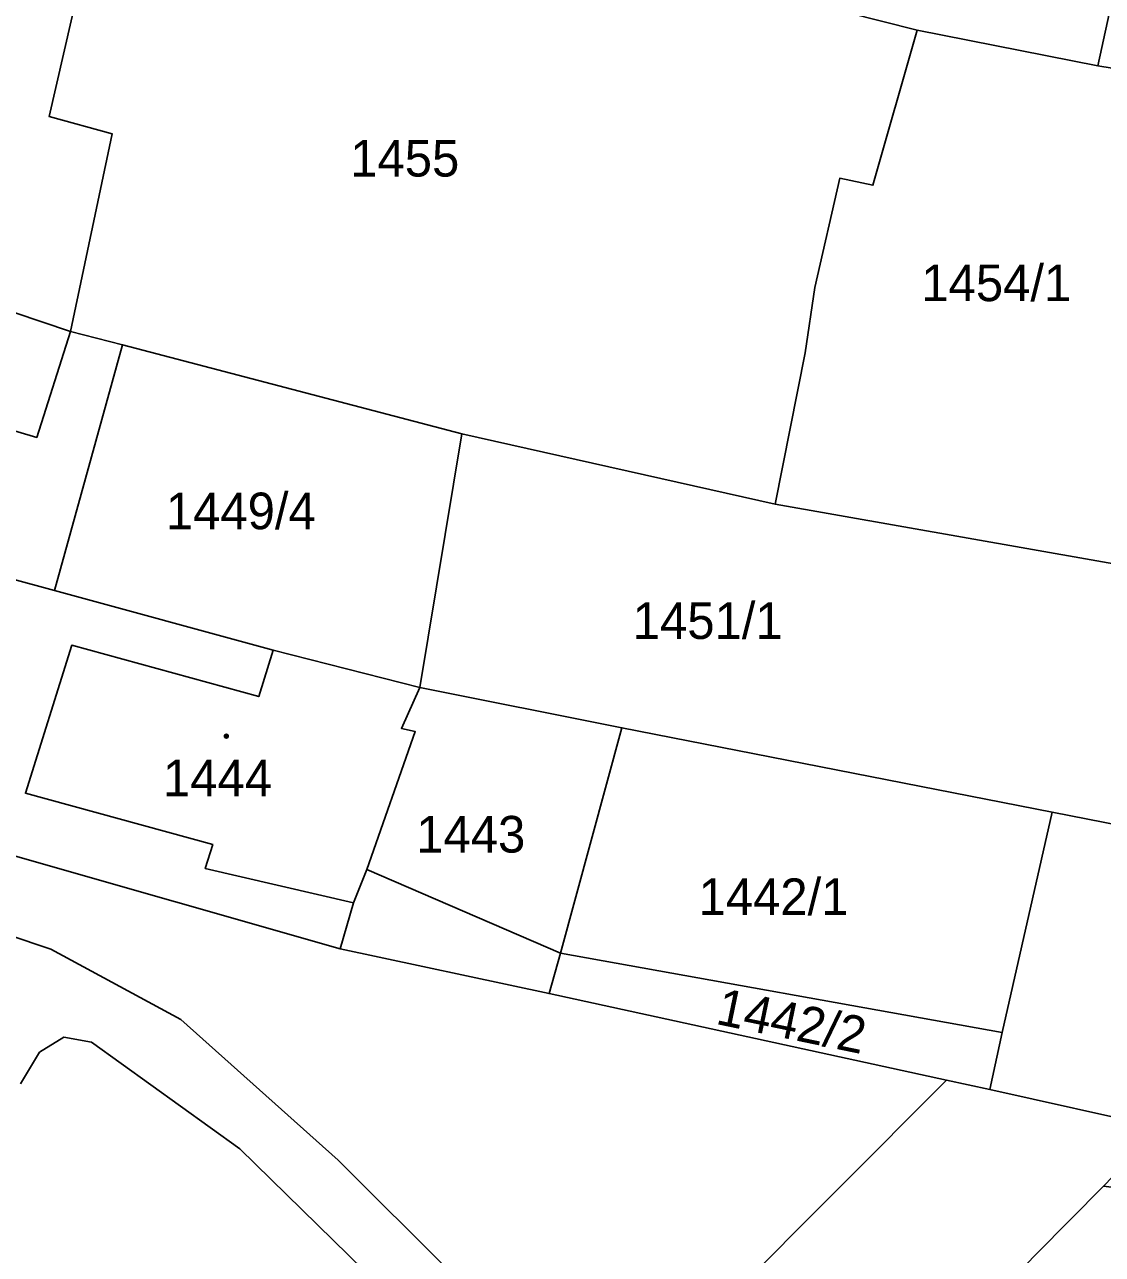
# Model space of a CAD drawing. Extents: x -598934 to -598196, y -1162208 to -1161502.
# Drawn here: x -598595 to -598545.1, y -1161658.4 to -1161601.3 of the extents above; entities that cross this region are included whole.
import ezdxf

# ---------------------------------------------------------------- set-up
doc = ezdxf.new("R2010")
doc.units = 0
for name, color, linetype in [('KN_CAR_KR', 7, 'Continuous'), ('KN_KULTURY', 7, 'Continuous'), ('KN_PARC_CIS_POZ', 7, 'Continuous'), ('KN_PARC_CIS_STAV', 7, 'Continuous'), ('KN_PARC_PLOCHA', 7, 'Continuous'), ('parcely_l', 7, 'Continuous')]:
    doc.layers.add(name, color=color, linetype=linetype)

msp = doc.modelspace()

# ---------------------------------------------------------------- linework, layer by layer
at = {"layer": 'KN_CAR_KR'}
for points in [[(-598609.95, -1161638.83), (-598593.83, -1161644.24)], [(-598570.2, -1161644.42), (-598579.17, -1161640.54)], [(-598593.83, -1161644.24), (-598587.8, -1161647.5)], [(-598587.8, -1161647.5), (-598580.5, -1161654.03)], [(-598593.22, -1161648.32), (-598594.36, -1161649.02)], [(-598591.94, -1161648.56), (-598593.22, -1161648.32)], [(-598595.24, -1161650.49), (-598594.36, -1161649.02)], [(-598591.94, -1161648.56), (-598585.06, -1161653.5)], [(-598585.06, -1161653.5), (-598578.58, -1161659.86)], [(-598580.5, -1161654.03), (-598570, -1161664.51)]]:
    msp.add_lwpolyline(points, dxfattribs=at)
at = {"layer": 'KN_KULTURY'}
for radius in [0.09, 0.0398]:
    msp.add_circle((-598585.69, -1161634.36), radius, dxfattribs=at)
at = {"layer": 'KN_PARC_PLOCHA'}
for points in [[(-598624.11, -1161581.44), (-598590.84, -1161592.28), (-598593.9, -1161605.62), (-598590.99, -1161606.41), (-598592.92, -1161615.58), (-598602.01, -1161612.53), (-598617.23, -1161607.95), (-598636.32, -1161601.91), (-598641.28, -1161599.7), (-598647.1, -1161597.16), (-598637.58, -1161576.44), (-598633.95, -1161578.1), (-598624.47, -1161581.28)], [(-598579.26, -1161595.13), (-598553.66, -1161601.61), (-598555.71, -1161608.8), (-598557.25, -1161608.48), (-598558.4, -1161613.55), (-598558.85, -1161616.58), (-598560.25, -1161623.59), (-598574.77, -1161620.33), (-598590.51, -1161616.21), (-598592.92, -1161615.58), (-598590.99, -1161606.41), (-598593.9, -1161605.62), (-598590.84, -1161592.28)], [(-598592.92, -1161615.58), (-598594.48, -1161620.5), (-598604.3, -1161617.58), (-598628.19, -1161609.89), (-598632.34, -1161608.56), (-598633.12, -1161611.11), (-598637.33, -1161609.86), (-598636.53, -1161607.17), (-598642.58, -1161605.23), (-598641.28, -1161599.7), (-598636.32, -1161601.91), (-598617.23, -1161607.95), (-598602.01, -1161612.53)], [(-598545.28, -1161603.26), (-598535.01, -1161604.94), (-598537.19, -1161614.99), (-598538.62, -1161621.3), (-598528.73, -1161622.73), (-598511.79, -1161625.27), (-598511.94, -1161626.55), (-598512.59, -1161630.77), (-598532.32, -1161628.19), (-598533.65, -1161628.02), (-598539.63, -1161627.23), (-598560.25, -1161623.59), (-598558.85, -1161616.58), (-598558.4, -1161613.55), (-598557.25, -1161608.48), (-598555.71, -1161608.8), (-598553.66, -1161601.61)], [(-598590.51, -1161616.21), (-598593.66, -1161627.61), (-598606.12, -1161624.21), (-598604.3, -1161617.58), (-598594.48, -1161620.5), (-598592.92, -1161615.58)], [(-598574.77, -1161620.33), (-598576.72, -1161632.1), (-598583.52, -1161630.37), (-598593.66, -1161627.61), (-598590.51, -1161616.21)], [(-598560.25, -1161623.59), (-598539.63, -1161627.23), (-598533.65, -1161628.02), (-598534.77, -1161635.43), (-598528.42, -1161636.39), (-598529.24, -1161640.79), (-598531.43, -1161640.62), (-598541.81, -1161638.99), (-598547.4, -1161637.89), (-598567.35, -1161633.97), (-598576.72, -1161632.1), (-598574.77, -1161620.33)], [(-598593.66, -1161627.61), (-598583.52, -1161630.37), (-598584.19, -1161632.52), (-598592.86, -1161630.14), (-598595.01, -1161637.01), (-598586.32, -1161639.39), (-598586.67, -1161640.5), (-598579.79, -1161642.09), (-598580.42, -1161644.22), (-598595.68, -1161639.87), (-598609.56, -1161636.18), (-598606.12, -1161624.21)], [(-598583.52, -1161630.37), (-598576.72, -1161632.1), (-598577.57, -1161634), (-598576.93, -1161634.15), (-598579.17, -1161640.54), (-598579.79, -1161642.09), (-598586.67, -1161640.5), (-598586.32, -1161639.39), (-598595.01, -1161637.01), (-598592.86, -1161630.14), (-598584.19, -1161632.52)], [(-598567.35, -1161633.97), (-598570.2, -1161644.42), (-598570.73, -1161646.3), (-598580.42, -1161644.22), (-598579.79, -1161642.09), (-598579.17, -1161640.54), (-598576.93, -1161634.15), (-598577.57, -1161634), (-598576.72, -1161632.1)], [(-598547.4, -1161637.89), (-598549.72, -1161648.11), (-598570.2, -1161644.42), (-598567.35, -1161633.97)], [(-598529.24, -1161640.79), (-598525.98, -1161640.94), (-598522, -1161641.16), (-598521.79, -1161641.35), (-598513.3, -1161649.15), (-598520.41, -1161657.62), (-598520.79, -1161657.48), (-598523.54, -1161655.94), (-598526.88, -1161655.45), (-598530.26, -1161654.98), (-598533.57, -1161654.46), (-598542.39, -1161652.51), (-598550.29, -1161650.75), (-598549.72, -1161648.11), (-598547.4, -1161637.89), (-598541.81, -1161638.99), (-598531.43, -1161640.62)], [(-598549.72, -1161648.11), (-598550.29, -1161650.75), (-598552.3, -1161650.32), (-598570.73, -1161646.3), (-598570.2, -1161644.42)], [(-598536.1, -1161656.95), (-598543.36, -1161664.75), (-598548.22, -1161669.81), (-598553.01, -1161665.26), (-598553.29, -1161665.01), (-598553.46, -1161664.69), (-598553.52, -1161664.38), (-598553.45, -1161663.96), (-598553.24, -1161663.61), (-598552.96, -1161663.37), (-598548.13, -1161658.38), (-598545.02, -1161655.24), (-598536.87, -1161656.25)]]:
    msp.add_lwpolyline(points, close=True, dxfattribs=at)
for points in [[(-598543.94, -1161597.07), (-598545.28, -1161603.26), (-598553.66, -1161601.61), (-598579.26, -1161595.13)], [(-598535.01, -1161604.94), (-598545.28, -1161603.26), (-598543.94, -1161597.07)], [(-598595.68, -1161639.87), (-598580.42, -1161644.22), (-598570.73, -1161646.3), (-598552.3, -1161650.32), (-598567.35, -1161665.43), (-598566.64, -1161668.59), (-598569.17, -1161671.33), (-598574.16, -1161676.83), (-598575.68, -1161679.47), (-598576.97, -1161682.25), (-598576.63, -1161683.85), (-598578.63, -1161685.88), (-598581.99, -1161689.3), (-598583.59, -1161690.6), (-598585.12, -1161691.58), (-598586.84, -1161692.34), (-598588.85, -1161692.9), (-598591.1, -1161693.15), (-598593.28, -1161693.23), (-598610.15, -1161693.51)], [(-598567.35, -1161665.43), (-598552.3, -1161650.32), (-598550.29, -1161650.75), (-598542.39, -1161652.51), (-598545.02, -1161655.24), (-598548.13, -1161658.38), (-598552.96, -1161663.37)]]:
    msp.add_lwpolyline(points, dxfattribs=at)
at = {"layer": 'parcely_l'}
for points in [[(-598590.84, -1161592.28), (-598593.9, -1161605.62), (-598590.99, -1161606.41), (-598592.92, -1161615.58)], [(-598579.26, -1161595.13), (-598553.66, -1161601.61)], [(-598545.28, -1161603.26), (-598543.94, -1161597.07), (-598543.73, -1161596.1), (-598530.32, -1161598.92), (-598528.99, -1161599.15), (-598527.81, -1161599.28), (-598524.69, -1161599.81), (-598524.6, -1161599.32), (-598521.85, -1161599.79), (-598521.93, -1161600.29), (-598508.64, -1161602.57), (-598508.36, -1161601.34), (-598504.59, -1161602.07), (-598504.44, -1161601.34), (-598501.46, -1161601.89), (-598501.58, -1161602.63), (-598499.54, -1161603.01), (-598499.42, -1161602.43), (-598497.61, -1161602.77), (-598497.84, -1161604), (-598491.6, -1161605.15), (-598491.49, -1161604.56), (-598488.59, -1161605.09), (-598490.04, -1161612.91)], [(-598592.92, -1161615.58), (-598602.01, -1161612.53), (-598617.23, -1161607.95), (-598636.32, -1161601.91), (-598641.28, -1161599.7)], [(-598560.25, -1161623.59), (-598558.85, -1161616.58), (-598558.4, -1161613.55), (-598557.25, -1161608.48), (-598555.71, -1161608.8), (-598553.66, -1161601.61)], [(-598553.66, -1161601.61), (-598545.28, -1161603.26)], [(-598545.28, -1161603.26), (-598535.01, -1161604.94)], [(-598592.92, -1161615.58), (-598594.48, -1161620.5), (-598604.3, -1161617.58)], [(-598592.92, -1161615.58), (-598590.51, -1161616.21)], [(-598593.66, -1161627.61), (-598590.51, -1161616.21)], [(-598590.51, -1161616.21), (-598574.77, -1161620.33)], [(-598574.77, -1161620.33), (-598576.72, -1161632.1)], [(-598574.77, -1161620.33), (-598560.25, -1161623.59)], [(-598560.25, -1161623.59), (-598539.63, -1161627.23), (-598533.65, -1161628.02)], [(-598593.66, -1161627.61), (-598606.12, -1161624.21)], [(-598583.52, -1161630.37), (-598593.66, -1161627.61)], [(-598583.52, -1161630.37), (-598584.19, -1161632.52), (-598592.86, -1161630.14), (-598595.01, -1161637.01), (-598586.32, -1161639.39), (-598586.67, -1161640.5), (-598579.79, -1161642.09)], [(-598576.72, -1161632.1), (-598583.52, -1161630.37)], [(-598579.79, -1161642.09), (-598579.17, -1161640.54), (-598576.93, -1161634.15), (-598577.57, -1161634), (-598576.72, -1161632.1)], [(-598567.35, -1161633.97), (-598576.72, -1161632.1)], [(-598570.2, -1161644.42), (-598567.35, -1161633.97)], [(-598547.4, -1161637.89), (-598567.35, -1161633.97)], [(-598580.42, -1161644.22), (-598595.68, -1161639.87), (-598609.56, -1161636.18)], [(-598547.4, -1161637.89), (-598549.72, -1161648.11)], [(-598529.24, -1161640.79), (-598531.43, -1161640.62), (-598541.81, -1161638.99), (-598547.4, -1161637.89)], [(-598579.79, -1161642.09), (-598580.42, -1161644.22)], [(-598580.42, -1161644.22), (-598570.73, -1161646.3)], [(-598570.73, -1161646.3), (-598570.2, -1161644.42)], [(-598549.72, -1161648.11), (-598570.2, -1161644.42)], [(-598552.3, -1161650.32), (-598570.73, -1161646.3)], [(-598549.72, -1161648.11), (-598550.29, -1161650.75)], [(-598552.3, -1161650.32), (-598567.35, -1161665.43), (-598566.64, -1161668.59), (-598569.17, -1161671.33), (-598574.16, -1161676.83), (-598575.68, -1161679.47), (-598576.97, -1161682.25), (-598576.63, -1161683.85), (-598578.63, -1161685.88), (-598581.99, -1161689.3), (-598583.59, -1161690.6), (-598585.12, -1161691.58), (-598586.84, -1161692.34), (-598588.85, -1161692.9), (-598591.1, -1161693.15), (-598593.28, -1161693.23), (-598610.15, -1161693.51)], [(-598550.29, -1161650.75), (-598552.3, -1161650.32)], [(-598550.29, -1161650.75), (-598542.39, -1161652.51)], [(-598553.45, -1161663.96), (-598553.24, -1161663.61), (-598552.96, -1161663.37), (-598548.13, -1161658.38), (-598545.02, -1161655.24)]]:
    msp.add_lwpolyline(points, dxfattribs=at)

# ---------------------------------------------------------------- texts
at = {"layer": 'KN_PARC_CIS_POZ'}
for s, p in [('1455', (-598579.947, -1161608.4)), ('1454/1', (-598553.467, -1161614.18)), ('1449/4', (-598588.497, -1161624.76)), ('1451/1', (-598566.847, -1161629.85)), ('1443', (-598576.887, -1161639.76)), ('1442/1', (-598563.797, -1161642.66))]:
    msp.add_text(s, height=1.7, dxfattribs=at).set_placement(p)
msp.add_text('1442/2', height=1.7, rotation=348.3001, dxfattribs=at).set_placement((-598563.05, -1161647.7))
at = {"layer": 'KN_PARC_CIS_STAV'}
msp.add_text('1444', height=1.7, dxfattribs=at).set_placement((-598588.632, -1161637.15))

doc.saveas('drawing.dxf')
